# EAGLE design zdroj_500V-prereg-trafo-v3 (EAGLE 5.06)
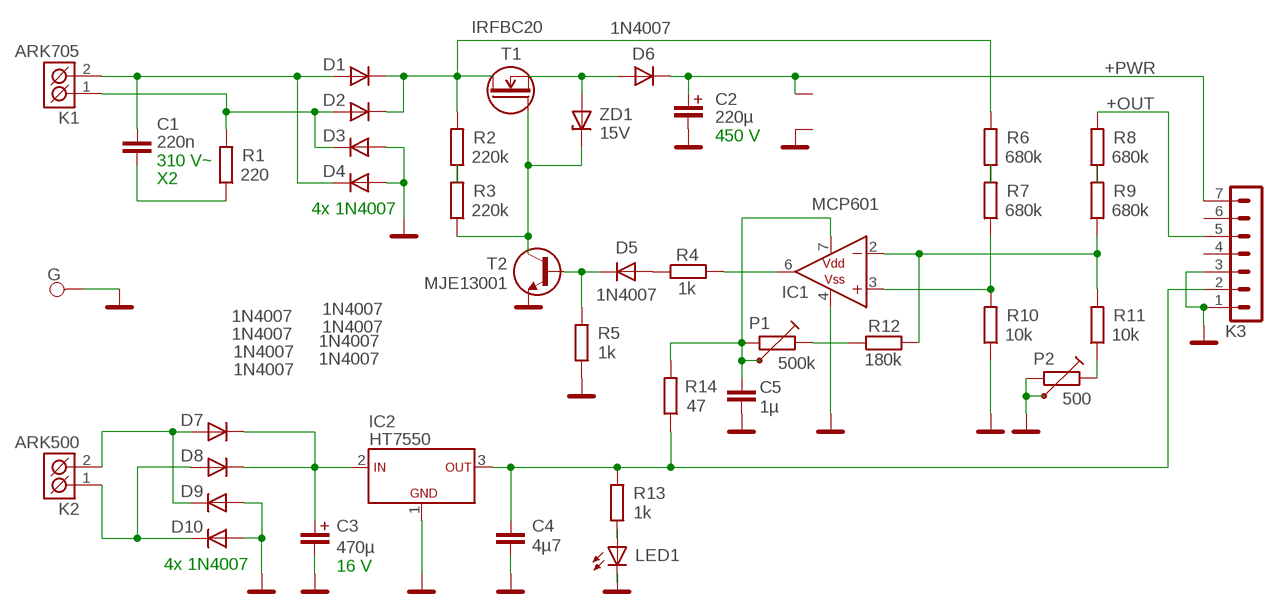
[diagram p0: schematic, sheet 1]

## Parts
C1  220n  C_CFAC_220N_X2  [CFAC_220N_X2]
C2  220µ  C_ELYT_10-35_SNAP-IN  [CEL_10-35_SNAP-IN]
C3  470µ  C_ELYT_5-10  [CEL_5-10]
C4  4µ7  C_KER_RM5  [C_KER_RM5]
C5  1µ  C_KER_RM5  [C_KER_RM5]
D1  1N4007  DIODADO41_(1N40XX)-7MM  [DO41-7]
D2  1N4007  DIODADO41_(1N40XX)-7MM  [DO41-7]
D3  1N4007  DIODADO41_(1N40XX)-7MM  [DO41-7]
D4  1N4007  DIODADO41_(1N40XX)-7MM  [DO41-7]
D5  1N4007  DIODADO35_(1N4148)-7MM  [DO35-7]
D6  1N4007  DIODADO41_(1N40XX)-7MM  [DO41-7]
D7  1N4007  DIODADO41_(1N40XX)-7MM  [DO41-7]
D8  1N4007  DIODADO41_(1N40XX)-7MM  [DO41-7]
D9  1N4007  DIODADO41_(1N40XX)-7MM  [DO41-7]
D10  1N4007  DIODADO41_(1N40XX)-7MM  [DO41-7]
G  PAD_1_2.54/1.4MM  [PAD_1]
IC1  MCP601  OZ-1X_5PIN_DIL8  [DIL08]
IC2  HT7550  79L_HT7133  [TO-92]
K1  ARK705  SVORKOVNICE_2P_ARK705  [ARK705/2]
K2  ARK500  SVORKOVNICE_2P_ARK500  [ARK500/2]
K3  KONZ-07PSH02  [PSH02-07]
LED1  LED3MM  [LED3MM]
P1  500k  R-TRIMRPT6V  [PT6V]
P2  500  R-TRIMRPT6V  [PT6V]
R1  220  REZISTOR_411-15  [0411-15]
R2  220k  REZISTOR_207-10  [207-10]
R3  220k  REZISTOR_207-10  [207-10]
R4  1k  REZISTOR_207-10  [207-10]
R5  1k  REZISTOR_207-10  [207-10]
R6  680k  REZISTOR_207-10  [207-10]
R7  680k  REZISTOR_207-10  [207-10]
R8  680k  REZISTOR_207-10  [207-10]
R9  680k  REZISTOR_207-10  [207-10]
R10  10k  REZISTOR_207-10  [207-10]
R11  10k  REZISTOR_207-10  [207-10]
R12  180k  REZISTOR_207-10  [207-10]
R13  1k  REZISTOR_207-10  [207-10]
R14  47  REZISTOR_207-10  [207-10]
T1  IRFBC20  T_NFETTO220  [TO220_V]
T2  MJE13001  T_NPNTO92-BCE  [TO92-BCE]
U$1  2_PINY_BEZ_POTISKU_5MM  [2_PINY_BEZ_POTISKU_RM5]
ZD1  15V  DIODA_ZENER_DO35-7  [DO35-7]

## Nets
+OUT: K3.5 R8.2
+PWR: C2.+ D6.K K3.7 U$1.P$1(P1)
GND: C2.- C3.- C4.2 C5.2 D3.A D4.A D9.A D10.A G.1 IC1.4(VSS) IC2.1(GND) K3.1 K3.3 LED1.K(C) P2.1 P2.3 R5.1 R10.1 T2.E U$1.P$2(P2)
N$1: LED1.A R13.1
N$2: IC1.2(-IN) R9.1 R11.2 R12.2
N$3: D7.A D9.K K2.2(K2)
N$4: C1.P$1 D1.A D4.K K1.2(K2)
N$5: D8.A D10.K K2.1(K1)
N$7: C4.1 IC2.3(OUT) K3.2 R13.2 R14.1
N$8: D2.A D3.K K1.1(K1) R1.2
N$9: D1.K D2.K R2.2 R6.2 T1.2(D)
N$10: C1.P$2 R1.1
N$11: R3.1 T1.1(G) T2.C ZD1.K
N$12: P1.2 R12.1
N$13: R2.1 R3.2
N$14: C5.1 IC1.7(VDD) P1.1 P1.3 R14.2
N$15: D6.A T1.3(S) ZD1.A
N$17: R8.1 R9.2
N$19: C3.+ D7.K D8.K IC2.2(IN)
N$21: R6.1 R7.2
N$23: IC1.3(+IN) R7.1 R10.2
N$24: P2.2 R11.1
N$25: IC1.6(OUT) R4.2
N$27: D5.A R4.1
N$35: D5.K R5.2 T2.B
Unconnected: K3.4 K3.6

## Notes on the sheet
- 450 V
- 310 V~
- X2
- 4x 1N4007
- 4x 1N4007 | 16 V

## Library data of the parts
C1 C4 C5 = #bcs7d:C: Kondenzatory, keramicke a foliove
C2 C3 = #bcs7d:C_ELYT: Kondenzatory, elektrolyticke
D1-D10 = #bcs7d:DIODA
G = #bcs7d:PAD_1: Pajeci bod - 2,54 mm prumer
IC1 = #bcs-ic1:OZ-1X_5PIN
IC2 = #bcs-ic1:79L_HT7133: Stabilizátor - zaporny - 100mA ?? - napeti - zaporne => 05, 08, 09, 12, 15, 18
K1 K2 = #bcs_pinhead:SVORKOVNICE_2P_: Svorkovnice 2 piny
K3 = #bcs_pinhead:KONZ-07: Konektory se zamkem - vidlice - 7pin
LED1 = #bcs7d:LED: LED
P1 P2 = #bcs7d:R-TRIMR
R1-R14 = #bcs7d:REZISTOR_
T1 = #bcs7d:T_NFET: N-FET
T2 = #bcs7d:T_NPN: NPN tranzistor
U$1 = #bcs_co_se_jinam_nehodi:2_PINY_BEZ_POTISKU
ZD1 = #bcs7d:DIODA_ZENER

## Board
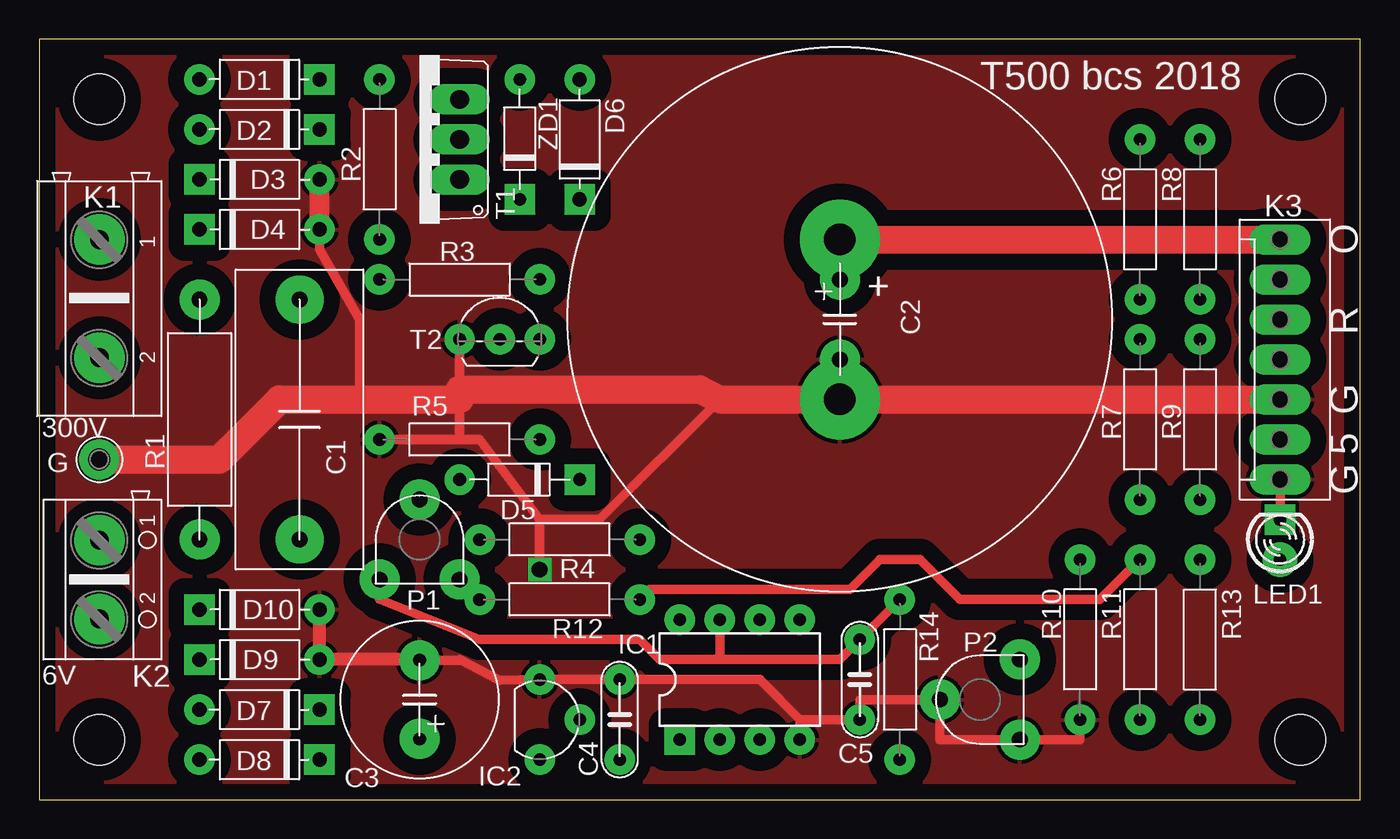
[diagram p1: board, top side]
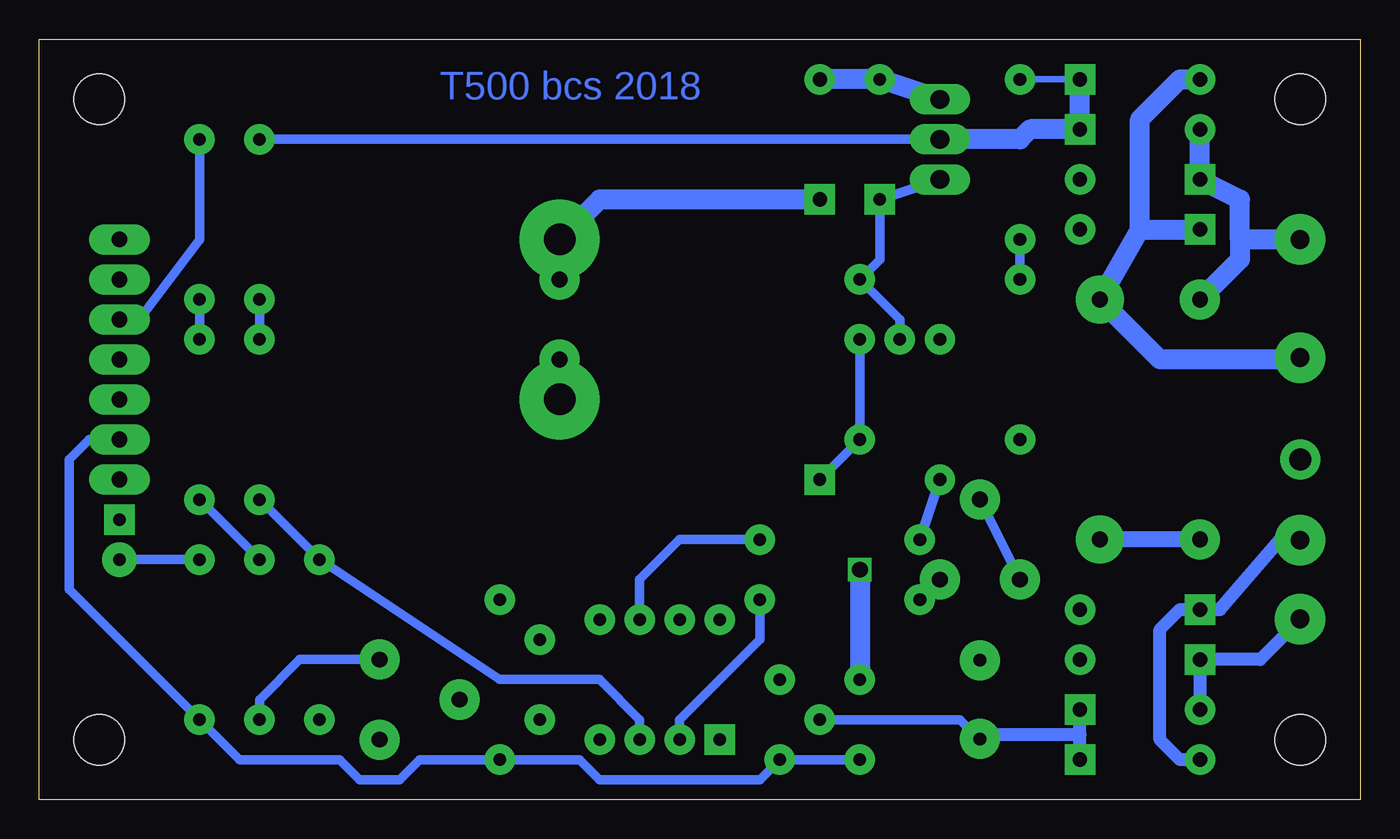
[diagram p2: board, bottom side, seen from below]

Size 83.82 x 48.26 mm. Coordinates in mm from the lower left corner, seen from the top.
Outline: 0,0 83.82,0 83.82,48.26 0,48.26 0,0
Copper layers (1*16): Top 0.035mm / dielectric 1.5mm / Bottom 0.035mm
Design rules "default": minimum track width 10mil, minimum drill 24mil, track to track 8mil, track to pad 8mil, pad to pad 8mil, via to via 8mil, smd to smd 8mil, copper to edge 40mil, drill to drill 8mil, minimum pad ring 10mil, minimum via ring 8mil, stop-mask expansion 4mil, vias tented up to drill 0mil, thermal gap 10mil
Holes 3.2 mm at 3.81,3.81 3.81,44.45 80.01,3.81 80.01,44.45

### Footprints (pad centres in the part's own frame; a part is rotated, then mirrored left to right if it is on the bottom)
CFAC_220N_X2 = drill 1 pad 3.048 round: P$1 -7.62,0; P$2 7.62,0
CEL_10-35_SNAP-IN = drill 2 pad 5.08 round: + -5.08,0; - 5.08,0
CEL_5-10 = drill 0.8 pad 2.54 round: + -2.5,0; - 2.5,0
C_KER_RM5 = drill 0.8 pad 1.93 round: 1 -2.54,0; 2 2.54,0
DO41-7 = drill 0.9 pad 1.93 round: A 7.62,0 | drill 0.9 pad 1.93 square: K 0,0
DO35-7 = drill 0.8 pad 1.93 round: A 3.81,0 | drill 0.8 pad 1.93 square: K -3.81,0
PAD_1 = drill 1.4 pad 2.54 round: 1 0,0
DIL08 = drill 0.8 pad 1.93 square: 1 -3.81,-3.81 | drill 0.8 pad 1.93 round: 2 -1.27,-3.81; 3 1.27,-3.81; 4 3.81,-3.81; 5 3.81,3.81; 6 1.27,3.81; 7 -1.27,3.81; 8 -3.81,3.81
TO-92 = drill 0.8 pad 1.93 round: 1 0,2.54; 2 2.54,0; 3 0,-2.54
ARK705/2 = drill 1.2 pad 3.2 round: 1 0,0; 2 7.5,0
ARK500/2 = drill 1.2 pad 3.2 round: 1 -2.5,0; 2 2.5,0
PSH02-07 = drill 1 pad 1.93 long: 1 -7.62,0; 2 -5.08,0; 3 -2.54,0; 4 0,0; 5 2.54,0; 6 5.08,0; 7 7.62,0
LED3MM = drill 0.8 pad 2.184 round: A -1.27,0 | drill 0.8 pad 1.93 square: K 1.27,0
PT6V = drill 1 pad 2.54 round: 1 -2.54,-2.54; 2 2.54,-2.54; 3 0,2.54
0411-15 = drill 1 pad 2.54 round: 1 -7.62,0; 2 7.62,0
207-10 = drill 0.8 pad 1.93 round: 1 -5.08,0; 2 5.08,0
TO220_V = drill 1.2 pad 1.93 long: 1 -2.54,-2.54; 2 0,-2.54; 3 2.54,-2.54
TO92-BCE = drill 0.8 pad 1.93 round: B 2.54,0; C 0,0; E -2.54,0
2_PINY_BEZ_POTISKU_RM5 = drill 1 pad 2.54 round: P$1 0,2.54; P$2 0,-2.54

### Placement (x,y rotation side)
C1  16.51,24.13 270 top
C2  50.8,30.48 270 top
C3  24.13,6.35 90 top
C4  36.83,5.08 90 top
C5  52.07,7.62 270 top
D1  17.78,45.72 180 top
D2  17.78,42.55 180 top
D3  10.16,39.37 0 top
D4  10.16,36.2 0 top
D5  30.48,20.32 180 top
D6  34.29,38.1 90 top
D7  17.78,5.71 180 top
D8  17.78,2.54 180 top
D9  10.16,8.89 0 top
D10  10.16,12.07 0 top
G  3.81,21.59 0 top
IC1  44.45,7.62 0 top
IC2  31.75,5.08 0 top
K1  3.81,35.56 270 top
K2  3.81,13.97 270 top
K3  78.74,27.94 90 top
LED1  78.74,16.51 90 top
P1  24.13,16.51 0 top
P2  59.69,6.35 90 top
R1  10.16,24.13 90 top
R2  21.59,40.64 90 top
R3  26.67,33.02 180 top
R4  33.02,16.51 0 top
R5  26.67,22.86 0 top
R6  69.85,36.83 90 top
R7  69.85,24.13 90 top
R8  73.66,36.83 90 top
R9  73.66,24.13 90 top
R10  66.04,10.16 90 top
R11  69.85,10.16 90 top
R12  33.02,12.7 0 top
R13  73.66,10.16 270 top
R14  54.61,7.62 90 top
T1  24.13,41.91 90 top
T2  29.21,29.21 0 top
U$1  50.8,30.48 0 top
ZD1  30.48,41.91 90 top

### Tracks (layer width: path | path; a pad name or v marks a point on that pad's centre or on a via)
+OUT
  Bottom 0.61: R8.2 73.66,35.56 77.47,30.48 K3.5
+PWR
  Top 1.778: C2.+ K3.7
  Bottom 0.406: C2.+ U$1.P$1
  Bottom 1.27: D6.K 48.26,38.1 C2.+
GND  (via drill 1)
  Top 0.406: C3.- 24.13,8.89 | D9.A
  Top 0.61: C3.- 26.63,8.85 26.67,8.89 29.21,7.58 IC2.1 C4.2 45.72,7.62 48.26,5.08 | LED1.K K3.1 | 48.26,5.08 IC1.4 | 48.26,5.08 C5.2 52.07,6.35 P2.3 57.15,3.81 P2.1 66.04,3.81 R10.1 | 26.67,22.86 R5.1 | 31.75,17.78 v31.75,14.61 | 31.75,17.78 27.94,22.86 26.67,22.86 | 43.18,25.4 35.56,17.78 31.75,17.78 | 20.32,25.4 20.32,30.48 17.78,34.92 D4.A | 26.67,22.86 26.67,26.04 T2.E
  Top 0.813: 24.13,8.89 D9.A D10.A
  Top 1.27: D4.A D3.A
  Top 1.778: K3.3 C2.- 43.18,25.4 41.91,26.04 26.67,26.04 26.67,25.4 20.32,25.4 15.24,25.4 11.43,21.59 G.1
  Bottom 0.406: C2.- U$1.P$2
  Bottom 1.27: v31.75,14.61 IC2.1
  pour Top (isolate 1.016): 0,48.26 83.82,48.26 83.82,0 0,0
N$1
  Bottom 0.61: R13.1 LED1.A
N$2
  Top 0.61: R12.2 38.73,13.34 51.44,13.34 53.34,15.24 55.88,15.24 58.42,12.7 67.31,12.7 R11.2
  Bottom 0.61: R12.2 38.1,10.16 43.18,5.08 IC1.2 | R11.2 R9.1
N$3
  Bottom 0.406: K2.2 3.81,11.43
  Bottom 0.813: 3.81,11.43 6.35,8.89 D9.K D7.A
N$4
  Bottom 0.406: K1.2 3.81,27.94
  Bottom 1.27: D1.A 11.43,45.72 13.97,43.18 13.97,36.2 | 13.97,36.2 D4.K | 13.97,36.2 C1.P$1 12.7,27.94 3.81,27.94
N$5
  Bottom 0.406: 3.85,16.51 K2.1 | 11.43,2.54 | D10.K | 8.89,12.06
  Bottom 0.813: D8.A 11.43,2.54 12.7,3.81 12.7,10.79 11.43,12.06 D10.K 8.89,12.06 5.08,16.51 3.85,16.51
N$7
  Bottom 0.61: IC2.3 C4.1 38.1,1.27 48.26,1.27 49.53,2.54 R14.1 59.69,2.54 60.96,1.27 63.5,1.27 64.77,2.54 71.12,2.54 R13.2 81.92,13.34 81.92,21.59 80.64,22.86 K3.2
N$8
  Bottom 1.27: D2.A D3.K 7.62,38.1 7.62,35.56 | R1.2 7.62,34.29 7.62,35.56 | K1.1 7.62,35.56
N$9
  Bottom 0.406: D1.K R2.2
  Bottom 0.61: T1.2 R6.2
  Bottom 1.27: D1.K D2.K 20.95,42.55 21.59,41.91 T1.2
N$10
  Bottom 1.016: R1.1 C1.P$2
N$11
  Bottom 0.61: T1.1 ZD1.K 30.48,34.29 R3.1 29.21,30.48 T2.C
N$12
  Bottom 0.61: P1.2 R12.1
N$13
  Bottom 0.61: R3.2 R2.1
N$14
  Top 0.61: 43.18,8.89 39.37,8.89 38.1,10.16 27.94,10.16 21.59,12.7 P1.1 | 43.18,8.89 IC1.7 | 43.18,8.89 50.8,8.89 C5.1 R14.2
  Bottom 0.61: P1.1 P1.3
N$15
  Bottom 1.27: T1.3 ZD1.A D6.A
N$17
  Bottom 0.61: R9.2 R8.1
N$19
  Bottom 0.61: 24.13,3.81 25.4,5.08 IC2.2
  Bottom 0.813: C3.+ 24.13,3.81 23.18,4.13 17.78,4.13 | 17.78,4.13 D7.K | D8.K 17.78,4.13
N$21
  Bottom 0.61: R7.2 R6.1
N$23
  Bottom 0.61: R7.1 R10.2 54.61,7.62 48.26,7.62 45.72,5.08 IC1.3
N$24
  Bottom 0.61: P2.2 67.31,8.89 69.85,6.35 R11.1
N$25
  Bottom 0.61: IC1.6 45.72,13.97 43.18,16.51 R4.2
N$27
  Bottom 0.61: R4.1 D5.A
N$35
  Bottom 0.61: D5.K R5.2 T2.B

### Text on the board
Bottom: T500 bcs 2018
tPlace: T500 bcs 2018 | O | + | R | G | 300V | 5 | G | 6V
